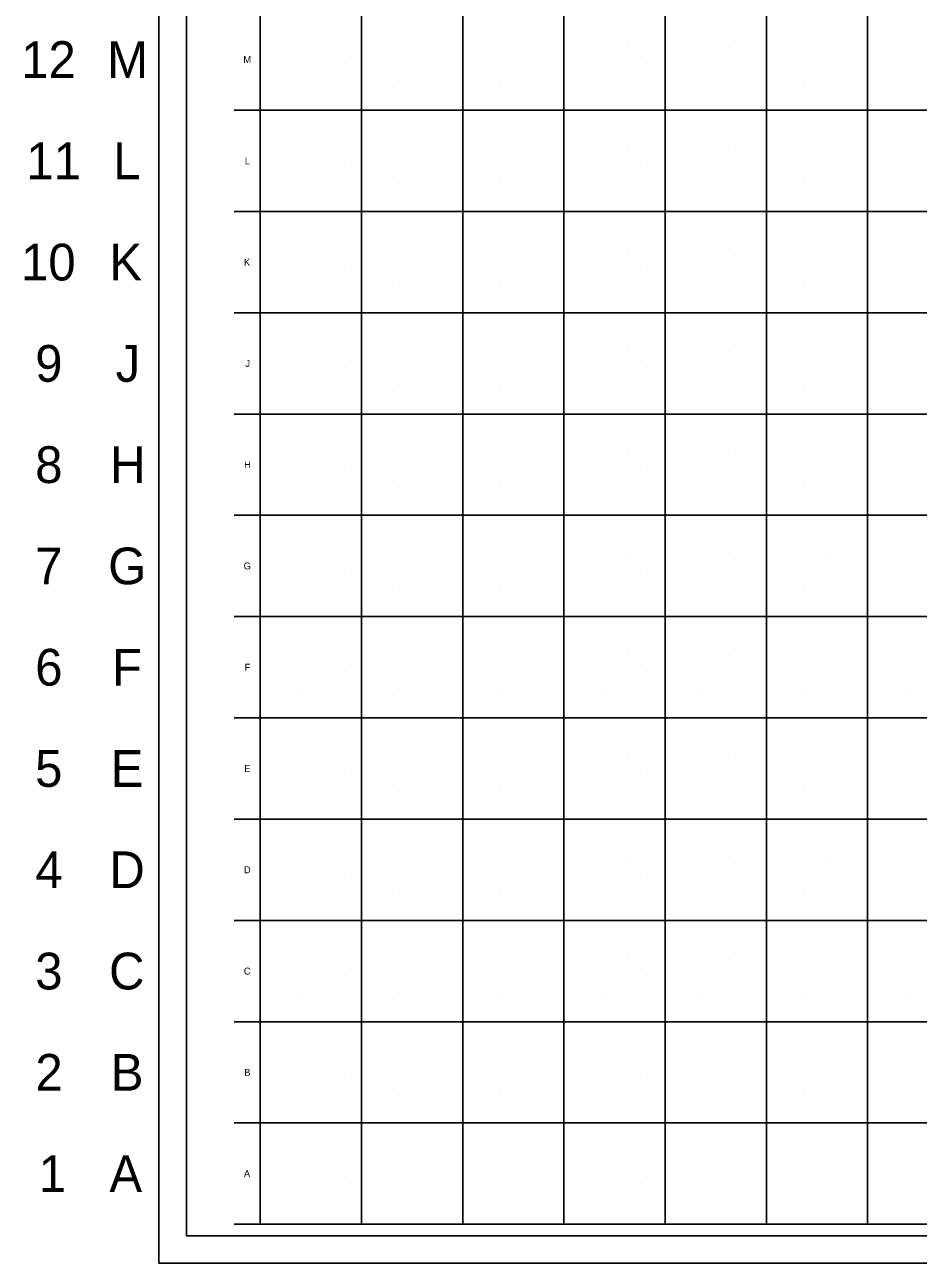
# Model space of a CAD drawing. Extents: x -0.05 to 1.19, y 0 to 0.86.
# Drawn here: x -0.0464 to 0.2626, y 0 to 0.428 of the extents above; entities that cross this region are included whole.
import ezdxf

# ---------------------------------------------------------------- set-up
doc = ezdxf.new("R2010")
doc.units = 0
for name, color, linetype in [('G-ANNO-NPLT', 7, 'Continuous'), ('G-ANNO-TEXT', 7, 'Continuous'), ('G-ANNO-TTLB', 7, 'Continuous'), ('G-ANNO-TTLB-GRID', 7, 'Continuous')]:
    doc.layers.add(name, color=color, linetype=linetype)

msp = doc.modelspace()

# ---------------------------------------------------------------- linework, layer by layer
at = {"layer": 'G-ANNO-NPLT'}
for p, q in [((0.16207, 0.42047), (0.16207, 0.42047)), ((0.19708, 0.42047), (0.19708, 0.42047)), ((0.23207, 0.42047), (0.23207, 0.42047)), ((0.06407, 0.41447), (0.06407, 0.41447)), ((0.09907, 0.41447), (0.09907, 0.41447)), ((0.13407, 0.41447), (0.13407, 0.41447)), ((0.16908, 0.41447), (0.16908, 0.41447)), ((0.20407, 0.41447), (0.20407, 0.41447)), ((0.23907, 0.41447), (0.23907, 0.41447)), ((0.04807, 0.40847), (0.04807, 0.40847)), ((0.08307, 0.40847), (0.08307, 0.40847)), ((0.11807, 0.40847), (0.11807, 0.40847)), ((0.15307, 0.40847), (0.15307, 0.40847)), ((0.18807, 0.40847), (0.18807, 0.40847)), ((0.22307, 0.40847), (0.22307, 0.40847)), ((0.25807, 0.40847), (0.25807, 0.40847)), ((0.16207, 0.38547), (0.16207, 0.38547)), ((0.19708, 0.38547), (0.19708, 0.38547)), ((0.23207, 0.38547), (0.23207, 0.38547)), ((0.06407, 0.37947), (0.06407, 0.37947)), ((0.09907, 0.37947), (0.09907, 0.37947)), ((0.13407, 0.37947), (0.13407, 0.37947)), ((0.16908, 0.37947), (0.16908, 0.37947)), ((0.20407, 0.37947), (0.20407, 0.37947)), ((0.23907, 0.37947), (0.23907, 0.37947)), ((0.04807, 0.37347), (0.04807, 0.37347)), ((0.08307, 0.37347), (0.08307, 0.37347)), ((0.11807, 0.37347), (0.11807, 0.37347)), ((0.15307, 0.37347), (0.15307, 0.37347)), ((0.18807, 0.37347), (0.18807, 0.37347)), ((0.22307, 0.37347), (0.22307, 0.37347)), ((0.25807, 0.37347), (0.25807, 0.37347)), ((0.16207, 0.35047), (0.16207, 0.35047)), ((0.19708, 0.35047), (0.19708, 0.35047)), ((0.23207, 0.35047), (0.23207, 0.35047)), ((0.06407, 0.34447), (0.06407, 0.34447)), ((0.09907, 0.34447), (0.09907, 0.34447)), ((0.13407, 0.34447), (0.13407, 0.34447)), ((0.16908, 0.34447), (0.16908, 0.34447)), ((0.20407, 0.34447), (0.20407, 0.34447)), ((0.23907, 0.34447), (0.23907, 0.34447)), ((0.04807, 0.33847), (0.04807, 0.33847)), ((0.08307, 0.33847), (0.08307, 0.33847)), ((0.11807, 0.33847), (0.11807, 0.33847)), ((0.15307, 0.33847), (0.15307, 0.33847)), ((0.18807, 0.33847), (0.18807, 0.33847)), ((0.22307, 0.33847), (0.22307, 0.33847)), ((0.25807, 0.33847), (0.25807, 0.33847)), ((0.16207, 0.31547), (0.16207, 0.31547)), ((0.19708, 0.31547), (0.19708, 0.31547)), ((0.23207, 0.31547), (0.23207, 0.31547)), ((0.06407, 0.30947), (0.06407, 0.30947)), ((0.09907, 0.30947), (0.09907, 0.30947)), ((0.13407, 0.30947), (0.13407, 0.30947)), ((0.16908, 0.30947), (0.16908, 0.30947)), ((0.20407, 0.30947), (0.20407, 0.30947)), ((0.23907, 0.30947), (0.23907, 0.30947)), ((0.04807, 0.30347), (0.04807, 0.30347)), ((0.08307, 0.30347), (0.08307, 0.30347)), ((0.11807, 0.30347), (0.11807, 0.30347)), ((0.15307, 0.30347), (0.15307, 0.30347)), ((0.18807, 0.30347), (0.18807, 0.30347)), ((0.22307, 0.30347), (0.22307, 0.30347)), ((0.25807, 0.30347), (0.25807, 0.30347)), ((0.16207, 0.28047), (0.16207, 0.28047)), ((0.19708, 0.28047), (0.19708, 0.28047)), ((0.23207, 0.28047), (0.23207, 0.28047)), ((0.06407, 0.27447), (0.06407, 0.27447)), ((0.09907, 0.27447), (0.09907, 0.27447)), ((0.13407, 0.27447), (0.13407, 0.27447)), ((0.16908, 0.27447), (0.16908, 0.27447)), ((0.20407, 0.27447), (0.20407, 0.27447)), ((0.23907, 0.27447), (0.23907, 0.27447)), ((0.04807, 0.26847), (0.04807, 0.26847)), ((0.08307, 0.26847), (0.08307, 0.26847)), ((0.11807, 0.26847), (0.11807, 0.26847)), ((0.15307, 0.26847), (0.15307, 0.26847)), ((0.18807, 0.26847), (0.18807, 0.26847)), ((0.22307, 0.26847), (0.22307, 0.26847)), ((0.25807, 0.26847), (0.25807, 0.26847)), ((0.16207, 0.24547), (0.16207, 0.24547)), ((0.19708, 0.24547), (0.19708, 0.24547)), ((0.23207, 0.24547), (0.23207, 0.24547)), ((0.06407, 0.23947), (0.06407, 0.23947)), ((0.09907, 0.23947), (0.09907, 0.23947)), ((0.13407, 0.23947), (0.13407, 0.23947)), ((0.16908, 0.23947), (0.16908, 0.23947)), ((0.20407, 0.23947), (0.20407, 0.23947)), ((0.23907, 0.23947), (0.23907, 0.23947)), ((0.04807, 0.23347), (0.04807, 0.23347)), ((0.08307, 0.23347), (0.08307, 0.23347)), ((0.11807, 0.23347), (0.11807, 0.23347)), ((0.15307, 0.23347), (0.15307, 0.23347)), ((0.18807, 0.23347), (0.18807, 0.23347)), ((0.22307, 0.23347), (0.22307, 0.23347)), ((0.25807, 0.23347), (0.25807, 0.23347)), ((0.16207, 0.21047), (0.16207, 0.21047)), ((0.19708, 0.21047), (0.19708, 0.21047)), ((0.23207, 0.21047), (0.23207, 0.21047)), ((0.06407, 0.20447), (0.06407, 0.20447)), ((0.09907, 0.20447), (0.09907, 0.20447)), ((0.13407, 0.20447), (0.13407, 0.20447)), ((0.16908, 0.20447), (0.16908, 0.20447)), ((0.20407, 0.20447), (0.20407, 0.20447)), ((0.23907, 0.20447), (0.23907, 0.20447)), ((0.04807, 0.19847), (0.04807, 0.19847)), ((0.08307, 0.19847), (0.08307, 0.19847)), ((0.11807, 0.19847), (0.11807, 0.19847)), ((0.15307, 0.19847), (0.15307, 0.19847)), ((0.18807, 0.19847), (0.18807, 0.19847)), ((0.22307, 0.19847), (0.22307, 0.19847)), ((0.25807, 0.19847), (0.25807, 0.19847)), ((0.16207, 0.17547), (0.16207, 0.17547)), ((0.19708, 0.17547), (0.19708, 0.17547)), ((0.23207, 0.17547), (0.23207, 0.17547)), ((0.06407, 0.16947), (0.06407, 0.16947)), ((0.09907, 0.16947), (0.09907, 0.16947)), ((0.13407, 0.16947), (0.13407, 0.16947)), ((0.16908, 0.16947), (0.16908, 0.16947)), ((0.20407, 0.16947), (0.20407, 0.16947)), ((0.23907, 0.16947), (0.23907, 0.16947)), ((0.04807, 0.16347), (0.04807, 0.16347)), ((0.08307, 0.16347), (0.08307, 0.16347)), ((0.11807, 0.16347), (0.11807, 0.16347)), ((0.15307, 0.16347), (0.15307, 0.16347)), ((0.18807, 0.16347), (0.18807, 0.16347)), ((0.22307, 0.16347), (0.22307, 0.16347)), ((0.25807, 0.16347), (0.25807, 0.16347)), ((0.16207, 0.14047), (0.16207, 0.14047)), ((0.19708, 0.14047), (0.19708, 0.14047)), ((0.23207, 0.14047), (0.23207, 0.14047)), ((0.06407, 0.13447), (0.06407, 0.13447)), ((0.09907, 0.13447), (0.09907, 0.13447)), ((0.13407, 0.13447), (0.13407, 0.13447)), ((0.16908, 0.13447), (0.16908, 0.13447)), ((0.20407, 0.13447), (0.20407, 0.13447)), ((0.23907, 0.13447), (0.23907, 0.13447)), ((0.04807, 0.12847), (0.04807, 0.12847)), ((0.08307, 0.12847), (0.08307, 0.12847)), ((0.11807, 0.12847), (0.11807, 0.12847)), ((0.15307, 0.12847), (0.15307, 0.12847)), ((0.18807, 0.12847), (0.18807, 0.12847)), ((0.22307, 0.12847), (0.22307, 0.12847)), ((0.25807, 0.12847), (0.25807, 0.12847)), ((0.16207, 0.10547), (0.16207, 0.10547)), ((0.19708, 0.10547), (0.19708, 0.10547)), ((0.23207, 0.10547), (0.23207, 0.10547)), ((0.06407, 0.09947), (0.06407, 0.09947)), ((0.09907, 0.09947), (0.09907, 0.09947)), ((0.13407, 0.09947), (0.13407, 0.09947)), ((0.16908, 0.09947), (0.16908, 0.09947)), ((0.20407, 0.09947), (0.20407, 0.09947)), ((0.23907, 0.09947), (0.23907, 0.09947)), ((0.04807, 0.09347), (0.04807, 0.09347)), ((0.08307, 0.09347), (0.08307, 0.09347)), ((0.11807, 0.09347), (0.11807, 0.09347)), ((0.15307, 0.09347), (0.15307, 0.09347)), ((0.18807, 0.09347), (0.18807, 0.09347)), ((0.22307, 0.09347), (0.22307, 0.09347)), ((0.25807, 0.09347), (0.25807, 0.09347)), ((0.06407, 0.06447), (0.06407, 0.06447)), ((0.09907, 0.06447), (0.09907, 0.06447)), ((0.13407, 0.06447), (0.13407, 0.06447)), ((0.16908, 0.06447), (0.16908, 0.06447)), ((0.20407, 0.06447), (0.20407, 0.06447)), ((0.23907, 0.06447), (0.23907, 0.06447)), ((0.04807, 0.05847), (0.04807, 0.05847)), ((0.08307, 0.05847), (0.08307, 0.05847)), ((0.11807, 0.05847), (0.11807, 0.05847)), ((0.15307, 0.05847), (0.15307, 0.05847)), ((0.18807, 0.05847), (0.18807, 0.05847)), ((0.22307, 0.05847), (0.22307, 0.05847)), ((0.25807, 0.05847), (0.25807, 0.05847)), ((0.06407, 0.02947), (0.06407, 0.02947)), ((0.09907, 0.02947), (0.09907, 0.02947)), ((0.13407, 0.02947), (0.13407, 0.02947)), ((0.16908, 0.02947), (0.16908, 0.02947)), ((0.20407, 0.02947), (0.20407, 0.02947)), ((0.23907, 0.02947), (0.23907, 0.02947))]:
    msp.add_line(p, q, dxfattribs=at)
msp.add_lwpolyline([(0.00952, 0.83147), (1.17948, 0.83147), (1.17948, 0.00952), (0.00952, 0.00952)], close=True, dxfattribs=at)
at = {"layer": 'G-ANNO-TEXT'}
for p, q in [((0.03507, 0.39847), (0.02601, 0.39847)), ((0.03507, 0.36347), (0.02601, 0.36347)), ((0.03507, 0.32847), (0.02601, 0.32847)), ((0.03507, 0.29347), (0.02601, 0.29347)), ((0.03507, 0.25847), (0.02601, 0.25847)), ((0.03507, 0.22347), (0.02601, 0.22347)), ((0.03507, 0.18847), (0.02601, 0.18847)), ((0.03507, 0.15347), (0.02601, 0.15347)), ((0.03507, 0.11847), (0.02601, 0.11847)), ((0.03507, 0.08347), (0.02601, 0.08347)), ((0.03507, 0.04847), (0.02601, 0.04847)), ((0.03507, 0.01347), (0.02601, 0.01347))]:
    msp.add_line(p, q, dxfattribs=at)
at = {"layer": 'G-ANNO-TTLB'}
for points in [[(0, 0.841), (1.189, 0.841), (1.189, 0), (0, 0)], [(0.03507, 0.81847), (1.17009, 0.81847), (1.17009, 0.01347), (0.03507, 0.01347)]]:
    msp.add_lwpolyline(points, close=True, dxfattribs=at)
at = {"layer": 'G-ANNO-TTLB-GRID'}
for p, q in [((0.07007, 0.81847), (0.07007, 0.01347)), ((0.10508, 0.81847), (0.10508, 0.01347)), ((0.14008, 0.81847), (0.14008, 0.01347)), ((0.17507, 0.81847), (0.17507, 0.01347)), ((0.21007, 0.81847), (0.21007, 0.01347)), ((0.24507, 0.81847), (0.24507, 0.01347)), ((0.03507, 0.39847), (1.12007, 0.39847)), ((0.03507, 0.36347), (1.12007, 0.36347)), ((0.03507, 0.32847), (1.12007, 0.32847)), ((0.03507, 0.29347), (1.12007, 0.29347)), ((0.03507, 0.25847), (1.12007, 0.25847)), ((0.03507, 0.22347), (1.12007, 0.22347)), ((0.03507, 0.18847), (1.12007, 0.18847)), ((0.03507, 0.15347), (1.12007, 0.15347)), ((0.03507, 0.11847), (1.12007, 0.11847)), ((0.03507, 0.08347), (1.12007, 0.08347)), ((0.03507, 0.04847), (1.12007, 0.04847))]:
    msp.add_line(p, q, dxfattribs=at)

# ---------------------------------------------------------------- texts
at = {"layer": 'G-ANNO-NPLT'}
for s, p in [('12', (-0.04762, 0.40962)), ('M', (-0.0179, 0.40962)), ('11', (-0.0458, 0.37462)), ('L', (-0.01579, 0.37462)), ('10', (-0.04766, 0.33962)), ('K', (-0.01708, 0.33962)), ('9', (-0.04276, 0.30462)), ('J', (-0.01493, 0.30462)), ('8', (-0.04276, 0.26962)), ('H', (-0.01687, 0.26962)), ('7', (-0.04275, 0.23462)), ('G', (-0.01752, 0.23462)), ('6', (-0.04275, 0.19962)), ('F', (-0.01619, 0.19962)), ('5', (-0.0428, 0.16462)), ('E', (-0.01662, 0.16462)), ('4', (-0.04272, 0.12962)), ('D', (-0.01711, 0.12962)), ('3', (-0.04275, 0.09462)), ('C', (-0.01723, 0.09462)), ('2', (-0.04269, 0.05962)), ('B', (-0.01662, 0.05962)), ('1', (-0.04152, 0.02462)), ('A', (-0.01711, 0.02462))]:
    msp.add_text(s, height=0.0127, dxfattribs=at).set_placement(p)
at = {"layer": 'G-ANNO-TEXT'}
for s, p in [('M', (0.02923, 0.41477)), ('L', (0.02973, 0.37977)), ('K', (0.02943, 0.34477)), ('J', (0.02993, 0.30977)), ('H', (0.02948, 0.27477)), ('G', (0.02932, 0.23977)), ('F', (0.02964, 0.20477)), ('E', (0.02953, 0.16977)), ('D', (0.02942, 0.13477)), ('C', (0.02939, 0.09977)), ('B', (0.02953, 0.06477)), ('A', (0.02942, 0.02977))]:
    msp.add_text(s, height=0.0024, dxfattribs=at).set_placement(p)

doc.saveas('drawing.dxf')
